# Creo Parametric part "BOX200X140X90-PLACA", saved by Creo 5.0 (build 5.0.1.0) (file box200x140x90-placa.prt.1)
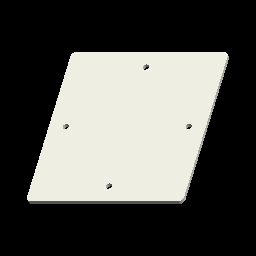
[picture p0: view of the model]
Units: millimeter Kilogram Sec (mmKs); MM, KILOGRAM, SECS
Materials in the file: ABS

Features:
  1. coordinate system "BOX200X140X90-PLACA"
  2. imported feature "Función De Importación ID 5"

Surfaces: 8 cone, 6 plane, 4 cylinder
